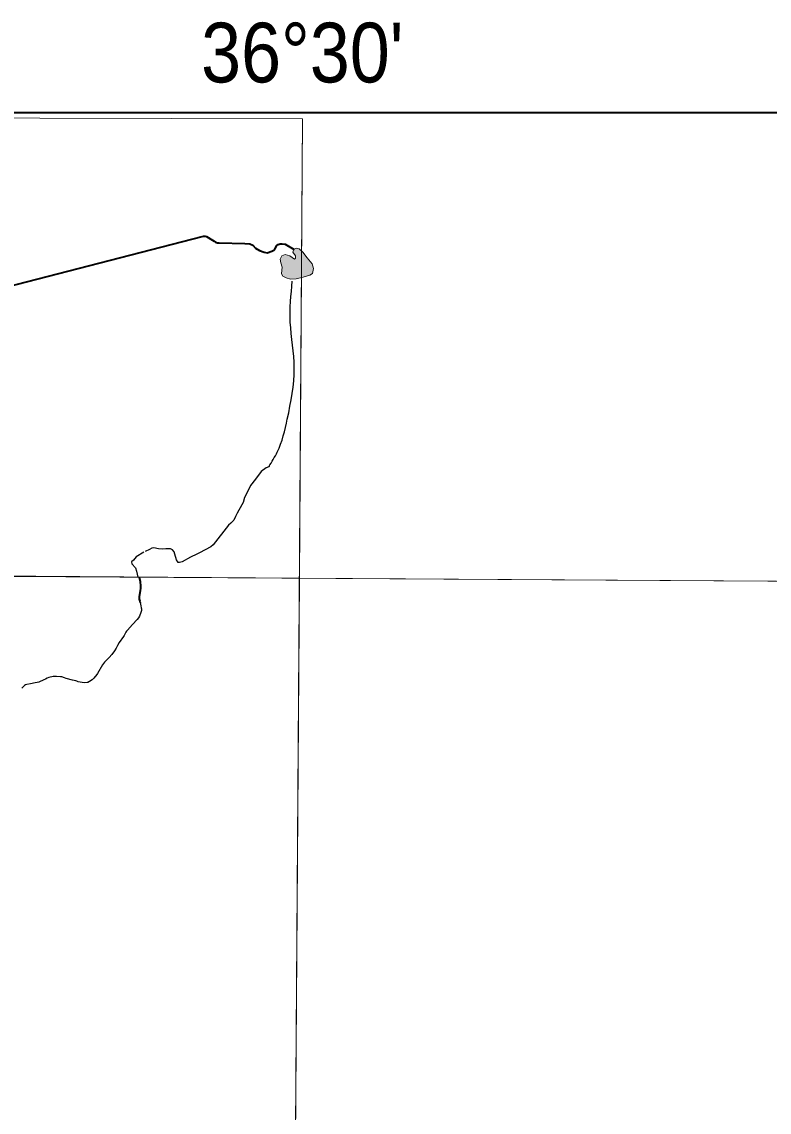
# Model space of a CAD drawing. Extents: x 553962 to 842807, y 8883888 to 9032388.
# Drawn here: x 616312 to 622569, y 8916398 to 8925528 of the extents above; entities that cross this region are included whole.
import ezdxf
from ezdxf.enums import TextEntityAlignment as Align

# ---------------------------------------------------------------- set-up
doc = ezdxf.new("R2010")
doc.units = 0
doc.header["$LTSCALE"] = 200
doc.layers.add('6', color=7, linetype='Continuous', lineweight=13)

msp = doc.modelspace()

# ---------------------------------------------------------------- hatches: boundary and pattern name
at = {"layer": '6'}
msp.add_hatch(color=256, dxfattribs=at).paths.add_polyline_path([(618590.4, 8923622.6), (618579.9, 8923599.2), (618603.3, 8923569.1), (618601.9, 8923550), (618595.2, 8923541.4), (618555.1, 8923567.6), (618516.4, 8923579.6), (618490.1, 8923569.1), (618473.9, 8923540.4), (618479.6, 8923509.8), (618492, 8923472.6), (618488.2, 8923448.2), (618485.8, 8923418.6), (618496.8, 8923398.6), (618526.4, 8923383.3), (618561.3, 8923372.8), (618610, 8923374.2), (618666.8, 8923390.9), (618723.7, 8923405.7), (618745.6, 8923421), (618754.2, 8923461.6), (618742.3, 8923501.7), (618701.7, 8923551.9), (618664, 8923597.7), (618633.9, 8923625.4), (618610.5, 8923632.6)])

# ---------------------------------------------------------------- linework, layer by layer
at = {"layer": '6', "lineweight": 35}
msp.add_lwpolyline([(574695.3, 8924769.6), (626625.7, 8924769.6), (626625.7, 8896026.7), (574695.3, 8896026.7)], close=True, dxfattribs=at)
at = {"layer": '6'}
for points in [[(607657.7, 8924743.3), (618663, 8924716.1), (618636, 8920869.6), (607600.8, 8920952.4)], [(618590.4, 8923622.6), (618579.9, 8923599.2), (618603.3, 8923569.1), (618601.9, 8923550), (618595.2, 8923541.4), (618555.1, 8923567.6), (618516.4, 8923579.6), (618490.1, 8923569.1), (618473.9, 8923540.4), (618479.6, 8923509.8), (618492, 8923472.6), (618488.2, 8923448.2), (618485.8, 8923418.6), (618496.8, 8923398.6), (618526.4, 8923383.3), (618561.3, 8923372.8), (618610, 8923374.2), (618666.8, 8923390.9), (618723.7, 8923405.7), (618745.6, 8923421), (618754.2, 8923461.6), (618742.3, 8923501.7), (618701.7, 8923551.9), (618664, 8923597.7), (618633.9, 8923625.4), (618610.5, 8923632.6)], [(618636, 8920869.6), (626625.7, 8920820.5), (626625.7, 8909822.1), (618558.7, 8909851.2)]]:
    msp.add_lwpolyline(points, close=True, dxfattribs=at)
for points in [[(618663, 8924716.1), (618558.3, 8909803.7), (618456.5, 8896026.7)], [(574684.9, 8921064.7), (596639.8, 8920989.8), (607636.3, 8920937.2), (626625.7, 8920820.5)]]:
    msp.add_lwpolyline(points, dxfattribs=at)
at = {"layer": '6', "lineweight": 40}
msp.add_lwpolyline([(614964.2, 8922992.9), (617832.6, 8923732.6), (617846.7, 8923732.8), (617858.9, 8923730.9), (617871.2, 8923721), (617893.7, 8923707.2), (617921.3, 8923691.5), (617934.6, 8923682.6), (617949.8, 8923677.8), (617965, 8923676), (618178.8, 8923671.4), (618220.3, 8923669), (618246.8, 8923657.3), (618269.5, 8923633.4), (618301.1, 8923613.7), (618341.8, 8923600.2), (618367.2, 8923594.5), (618405.5, 8923607.3), (618420.6, 8923616.6), (618432.5, 8923630.9), (618446.4, 8923654.4), (618458.4, 8923663.7), (618473.5, 8923670), (618492.7, 8923668.3), (618517.1, 8923664.6), (618591.3, 8923622.3)], dxfattribs=at)
at = {"layer": '6', "lineweight": 25}
for points in [[(618385.8, 8921803.1), (618379.3, 8921802.6), (618357.2, 8921792.1), (618316.2, 8921761.1), (618268.5, 8921697.7), (618226.7, 8921644.5), (618197.2, 8921585.4), (618177.6, 8921543.6), (618164, 8921504), (618129.5, 8921438.8), (618113.7, 8921413.2), (618101.9, 8921385.8), (618086.1, 8921356.2), (618063.2, 8921330.6), (618043.2, 8921312), (617913, 8921148.2), (617895, 8921131.8), (617799.5, 8921081.7), (617778.4, 8921071.3), (617725.1, 8921044.2), (617655.8, 8921005.7), (617632.6, 8921001.2), (617620.5, 8921001), (617607, 8921022.1), (617592.1, 8921070.3), (617586.7, 8921090.5), (617572.3, 8921107.4), (617556, 8921116.3), (617517.5, 8921115.6), (617491.2, 8921112.2), (617455.8, 8921114.7), (617418.2, 8921122.1), (617400, 8921119.8), (617381.9, 8921110.4), (617345.8, 8921092.5)], [(617334.2, 8921086.1), (617270.4, 8921047), (617247.5, 8921019.3), (617230.5, 8921004.9), (617231.8, 8920988.8), (617263.7, 8920954.9), (617272.2, 8920926.8), (617283, 8920878)], [(617303, 8920665.4), (617309.3, 8920639.1), (617311.5, 8920622.3), (617313.5, 8920613.9), (617313.6, 8920598.5), (617309.4, 8920583), (617298.1, 8920552.1), (617290.2, 8920537.8), (617278.2, 8920522.3), (617239.5, 8920482.6), (617196.2, 8920435), (617188.5, 8920425.5), (617182.5, 8920416.2), (617169.7, 8920388.5), (617163.2, 8920380.5), (617127.8, 8920330.6), (617112.8, 8920304.9), (617101.5, 8920282.3), (617087.7, 8920260.7), (617065.5, 8920231.4), (617042.8, 8920204.7), (617013.1, 8920175.2), (617003.5, 8920164.7), (616988.6, 8920143.8), (616945.6, 8920070.1), (616939.6, 8920064.2), (616914.7, 8920032.8), (616900.5, 8920019.1), (616878.8, 8920003.5), (616863.5, 8919995.6), (616858.6, 8919994.5), (616837.8, 8919993.2), (616816.9, 8919996.3), (616783.4, 8920002.8), (616773, 8920006.6), (616763.5, 8920011.1), (616735.6, 8920015.5), (616683.6, 8920028.8), (616669.3, 8920035.2), (616647.7, 8920042.1), (616635, 8920043.9), (616602.2, 8920045.9), (616583.8, 8920046.3), (616574.1, 8920045.7), (616539, 8920038.2), (616523, 8920032.3), (616509.2, 8920023.2), (616495.5, 8920017.5)], [(616495.5, 8920017.5), (616453.3, 8920000), (616409.4, 8919988.9), (616397.5, 8919986.6), (616384.8, 8919985.4), (616353, 8919979.2), (616343.8, 8919975.8), (616333.6, 8919969.7), (616322.5, 8919960.4), (616311.1, 8919948.7)]]:
    msp.add_lwpolyline(points, dxfattribs=at)
at = {"layer": '6', "lineweight": 35}
msp.add_lwpolyline([(617294.2, 8920878.4), (617302.4, 8920840.9), (617306.5, 8920803.1), (617306.1, 8920783.9), (617304, 8920766.2), (617295.2, 8920713.2), (617295.4, 8920693.6), (617300.5, 8920675.8), (617303, 8920665.4)], dxfattribs=at)
at = {"layer": '6', "lineweight": 25}
msp.add_spline([(618379.3, 8921802.6), (618451, 8921925.6), (618534.6, 8922201.8), (618593.2, 8922628.5), (618559.7, 8923013.4), (618576.4, 8923356.4)], degree=3, dxfattribs=at)

# ---------------------------------------------------------------- texts
at = {"layer": '6', "width": 0.9}
msp.add_text("36°30'", height=500, dxfattribs=at).set_placement((618660.1, 8925020.1), align=Align.CENTER)

doc.saveas('drawing.dxf')
